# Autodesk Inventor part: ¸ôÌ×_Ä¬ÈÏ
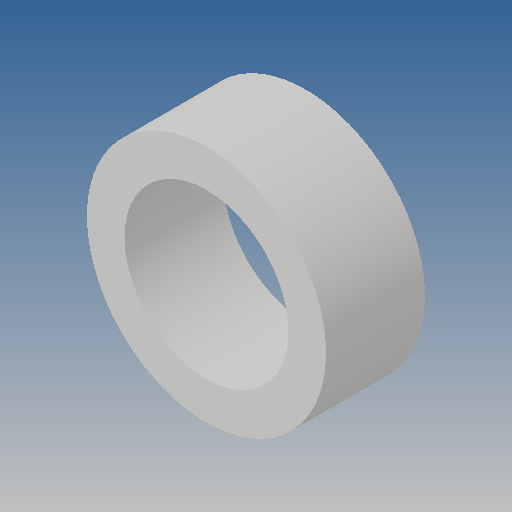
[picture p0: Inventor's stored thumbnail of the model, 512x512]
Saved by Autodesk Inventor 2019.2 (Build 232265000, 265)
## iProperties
Created: 2012-09
Part Number: ¸ôÌ×_Ä¬ÈÏ
Material: Ogólny
Document SubType Name: Modeling
Designer: CADENGINEERING4
Density: 1 g/cm^3
Appearance: Domyślna
Author: CADENGINEERING4
Revision Number: ÈÎºÎ
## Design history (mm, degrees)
feature "NONE"
node "Bryła1"
